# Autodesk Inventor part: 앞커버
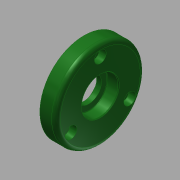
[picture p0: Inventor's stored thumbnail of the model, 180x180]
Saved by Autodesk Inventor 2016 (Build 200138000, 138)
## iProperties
Created: 2015-11
Part Number: 앞커버
Material: 알루미늄 6061
Document SubType Name: Modeling
Designer: mduedu
Density: 1 g/cm^3
Appearance: 매끄러움 - 짙은 산림 녹색
Author: mduedu
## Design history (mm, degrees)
sketch "스케치5"
  geometry: C1 r 30 at (0, 0); 2 further points
  constraints: 2 coincident, 1 centre point
  dimensions: "d66" = 60 diameter of C1
extrude "돌출2" new body sketch "스케치5" distance "d67" = 11; taper "d68" = 0 deg
sketch "스케치6"
  geometry: C1 r 16 at (0, 0); 1 further point
  constraints: 1 centre point, 1 coincident
  dimensions: "d69" = 32 diameter of C1
extrude "돌출3" join sketch "스케치6" distance "d70" = 3; taper "d71" = 0 deg
hole "구멍7" diameter "d98" = 25; stored, may be unused: countersink angle "d102" = 90 deg, drill point angle "d104" = 0 deg; dims "d96" = 10, "d97" = 10, "d99" = 6, "d100" = 4, "d101" = 2, "d103" = 3
hole "구멍8" diameter "d107" = 25; stored, may be unused: countersink angle "d111" = 90 deg, drill point angle "d113" = 0 deg; dims "d105" = 10, "d106" = 10, "d108" = 6, "d109" = 4, "d110" = 2, "d112" = 7.7
hole "구멍9" diameter "d116" = 17; stored, may be unused: countersink angle "d120" = 90 deg, drill point angle "d122" = 0 deg; dims "d114" = 10, "d115" = 10, "d117" = 6, "d118" = 4, "d119" = 2, "d121" = 7.7
chamfer "모따기2" distance "d123" = 0.6; stored, may be unused: second distance "d124" = 2, angle "d125" = 30 deg
fillet "모깎기11" dims "d126" = 0.3
fillet "모깎기13" dims "d128" = 3
fillet "모깎기14" dims "d129" = 3
fillet "모깎기15" dims "d130" = 0.3
sketch "스케치8" dims "d131" = 46
  geometry: 3 further points
  constraints: 2 vertical alignment, 1 coincident, 2 other
hole "구멍10" sketch "스케치8" at (0, 23) diameter "d132" = 4.5; stored, may be unused: countersink angle "d136" = 90 deg, drill point angle "d138" = 0 deg; dims "d133" = 6, "d134" = 8, "d135" = 4.6, "d137" = 7.7
node "솔리드2"
pattern_circular "원형 패턴4" dims angle "d140" = 360 deg
